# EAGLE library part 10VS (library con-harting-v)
CONNECTOR
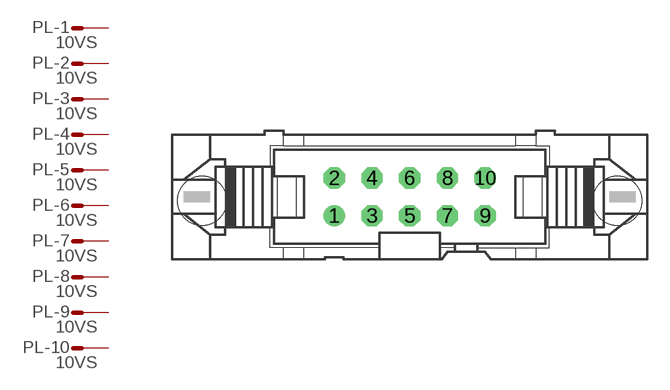
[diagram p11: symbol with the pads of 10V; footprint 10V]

Designator prefix PL; gates -1=M -2=M -3=M -4=M -5=M -6=M -7=M -8=M -9=M -10=M

## 10VS (OC_FARNELL: unknown; OC_NEWARK: unknown)  [10V]
1  -1:S  pas
2  -2:S  pas
3  -3:S  pas
4  -4:S  pas
5  -5:S  pas
6  -6:S  pas
7  -7:S  pas
8  -8:S  pas
9  -9:S  pas
10  -10:S  pas

## Footprint 10V (pad centres in mm)
CONNECTOR
drill 0.914 round: 1 -5.08,-1.27
drill 0.914 octagon: 2 -5.08,1.27; 3 -2.54,-1.27; 4 -2.54,1.27; 5 0,-1.27; 6 0,1.27; 7 2.54,-1.27; 8 2.54,1.27; 9 5.08,-1.27; 10 5.08,1.27
hole 3.302 at 13.97,-0.254
hole 3.302 at -13.97,-0.254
